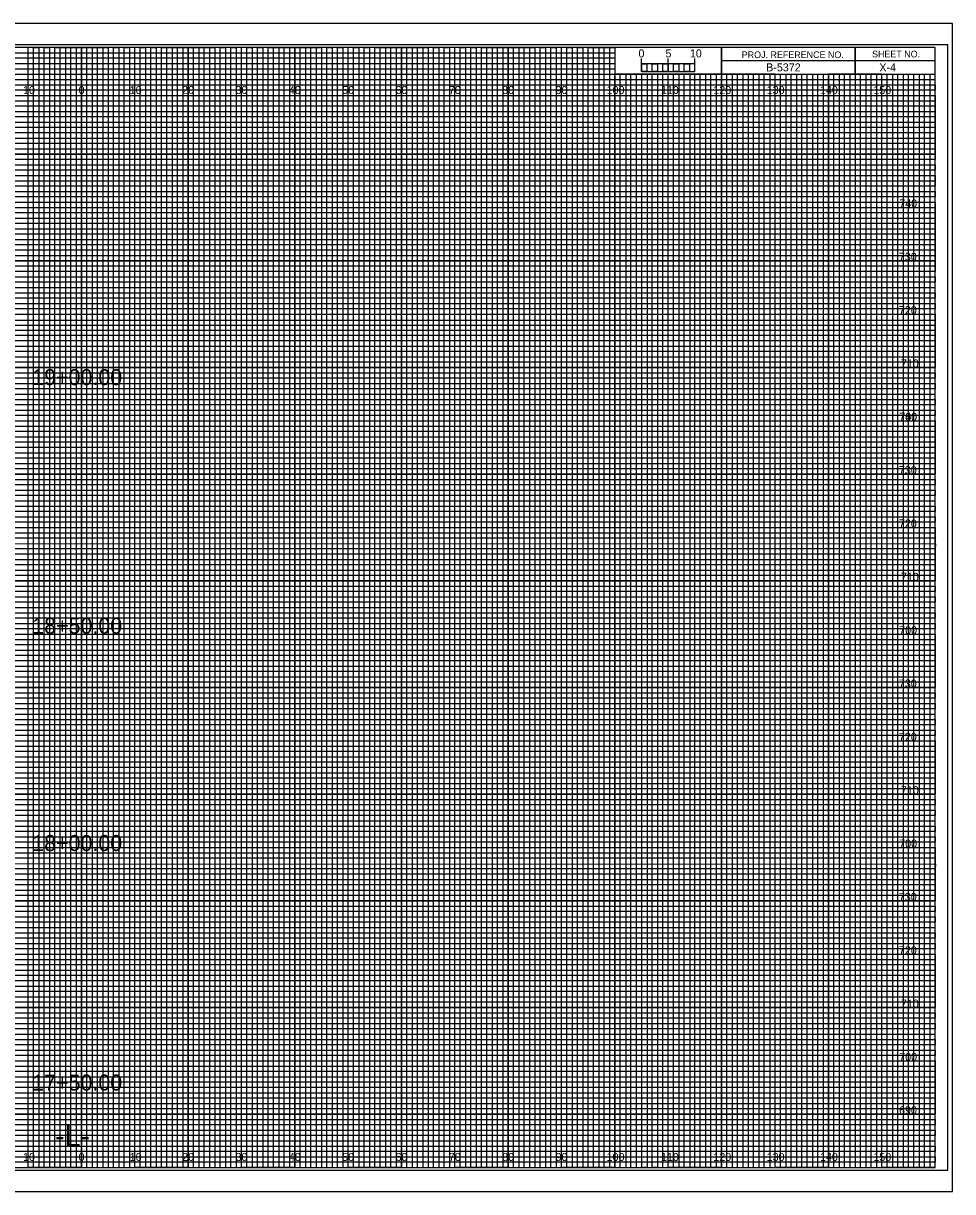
# Model space of a CAD drawing. Extents: x -98 to 717, y -10 to 1974.
# Drawn here: x 149.1 to 323.3, y 655.5 to 874.5 of the extents above; entities that cross this region are included whole.
import ezdxf

# ---------------------------------------------------------------- set-up
doc = ezdxf.new("R2010")
doc.units = 0
for name, color, linetype in [('Default', 7, 'Continuous'), ('Exist XS Center Line Elevation Label', 7, 'Continuous'), ('Prop CMT Conc Surface', 7, 'Continuous'), ('Prop CMT Concrete Structures', 7, 'Continuous'), ('Prop CMT Pvmt Course 1', 7, 'Continuous'), ('Prop CMT Pvmt Course 1 CG', 7, 'Continuous'), ('Prop CMT Pvmt Course 2', 7, 'Continuous'), ('Prop CMT Pvmt Course 3', 7, 'Continuous'), ('Prop CMT Pvmt Surface', 7, 'Continuous'), ('Prop CMT Pvmt Surface Shoulder', 7, 'Continuous'), ('Prop CMT Shld Paved Course 1', 7, 'Continuous'), ('Prop CMT Shld Paved Course 2', 7, 'Continuous'), ('Prop CMT Shld Paved Course 3', 7, 'Continuous'), ('Prop CMT Slope Grass', 7, 'Continuous'), ('Prop CMT Subgrade Earthwork', 7, 'Continuous'), ('Prop XS Earthwork Shape', 7, 'Continuous'), ('Prop XS Elevation Labels', 7, 'Continuous'), ('Typical Curb CELL', 7, 'Continuous')]:
    doc.layers.add(name, color=color, linetype=linetype)

msp = doc.modelspace()

# ---------------------------------------------------------------- linework, layer by layer
at = {"layer": 'Default'}
msp.add_lwpolyline([(-13.4, 655.5), (323.3, 655.5), (323.3, 874.5), (-13.4, 874.5)], close=True, dxfattribs=at)
at = {"layer": 'Exist XS Center Line Elevation Label'}
for p, q in [((0, 869), (260, 869)), ((260, 867.98), (0, 867.98)), ((260, 869), (260, 867.98)), ((0, 867), (260, 867)), ((260, 865.89), (0, 865.89)), ((260, 867), (260, 865.89)), ((0, 864), (320, 864))]:
    msp.add_line(p, q, dxfattribs=at)
for points in [[(0, 863), (270, 863), (320, 863), (320, 862), (0, 862)], [(0, 861), (320, 861), (320, 859), (0, 859)], [(0, 858), (320, 858), (320, 857), (0, 856.98)], [(0, 856), (320, 856), (320, 854), (0, 854)], [(0, 853), (320, 853), (320, 852), (0, 852)], [(0, 851), (320, 851), (320, 849), (0, 849)], [(0, 848), (320, 848), (320, 847), (0, 847)], [(0, 846), (320, 846), (320, 844), (0, 844)], [(0, 843), (320, 843), (320, 842), (0, 842)], [(0, 841), (320, 841), (320, 839), (0, 839)], [(0, 838), (320, 838), (320, 837), (0, 837)], [(0, 836), (320, 836), (320, 833.95), (320, 833), (320, 832), (0, 832)], [(0, 834), (320, 834), (320, 833), (0, 833)], [(0, 831), (320, 831), (320, 829), (0, 829.03)], [(0, 829.03), (320, 829), (320, 828), (0, 828)], [(0, 827), (320, 827), (320, 826), (0, 826)], [(0, 824), (320, 824), (320, 823), (0, 823)], [(0, 822), (320, 822), (320, 821), (0, 821)], [(-0.07, 818.89), (320, 818.89), (320, 817.88), (-0.07, 817.88)], [(0, 817), (320, 817), (320, 816), (0, 816)], [(0, 814), (320, 814), (320, 813), (0, 813)], [(0, 812), (320, 812), (320, 811), (0, 811)], [(0, 809), (320, 809), (320, 808), (0, 808)], [(0, 807), (320, 807), (320, 806), (0, 806)], [(0, 804), (320, 804), (320, 803), (0, 803)], [(0, 802), (320, 802), (320, 801), (0, 801)], [(0, 799), (320, 799), (319.99, 797.98), (0, 798)], [(0, 797), (320, 797), (320, 796), (0, 796)], [(0, 794), (320, 794), (320, 793), (0, 793)], [(0, 792), (320, 792), (320, 791), (0, 791)], [(0, 789), (320, 789), (320, 788), (0, 788)], [(0, 787), (320, 787), (320, 786), (0, 786)], [(0, 784), (320, 784), (320, 783), (0, 783)], [(0, 782), (320, 782), (320, 781), (0, 781)], [(0, 779), (320, 779), (320, 778), (0, 778)], [(0, 776.99), (320.07, 776.91), (320, 776), (0, 776)], [(0, 774), (320, 774), (320, 773), (0, 773)], [(0, 772), (320, 772), (320, 771), (0, 771)], [(0, 769), (320, 769), (320, 768), (0, 768)], [(0, 767), (320, 767), (320, 766), (0, 766)], [(0, 764), (320, 764), (320, 763), (0, 763)], [(0, 762), (320, 762), (320, 761), (0, 761)], [(0, 759), (320, 759), (320, 758), (0, 758)], [(0, 757), (320, 757), (320, 756), (0, 756)], [(0, 754), (320, 754), (320, 753), (0, 753)], [(0, 752), (320, 752), (320, 751), (0, 751)], [(0, 749), (320, 749), (320, 748), (0, 748)], [(0, 747), (320, 747), (320, 746), (0, 746)], [(0, 744), (320, 744), (320, 743), (0, 743)], [(0, 742), (320, 742), (320, 741), (0, 741)], [(0, 739), (320, 739), (319.99, 737.98), (0, 738)], [(0, 737), (320, 737), (320, 736), (0, 736)], [(0, 734), (320, 734), (320, 733), (0, 733)], [(0, 732), (320, 732), (320, 731), (0, 731)], [(0, 729), (320, 729), (320, 728), (0, 728)], [(0, 727), (320, 727), (320, 726), (0, 726)], [(0, 724), (320, 724), (320, 723), (0, 723)], [(0, 722), (320, 722), (320, 721), (0, 721)], [(0, 719), (320, 719), (320, 718), (0, 718)], [(0, 716.99), (320.07, 716.91), (320, 716), (0, 716)], [(0, 714), (320, 714), (320, 713), (0, 713)], [(0, 712), (320, 712), (320, 711), (0, 711)], [(0, 709), (320, 709), (320, 708), (0, 708)], [(0, 707), (320, 707), (320, 706), (0, 706)], [(0, 704), (320, 704), (320, 703), (0, 703)], [(0, 702), (320, 702), (320, 701), (0, 701)], [(0, 699), (320, 699), (320, 698), (0, 698)], [(0, 697), (320, 697), (320, 696), (0, 696)], [(0, 694), (320, 694), (320, 693), (0, 693)], [(0, 692), (320, 692), (320, 691), (0, 691)], [(0, 689), (320, 689), (320, 688), (0, 688)], [(0, 687), (320, 687), (320, 686), (0, 686)], [(0, 684), (320, 684), (320, 683), (0, 683)], [(0, 682), (320, 682), (320, 681), (0, 681)], [(0, 679), (320, 679), (320, 678), (0, 678)], [(0, 677), (320, 677), (320, 676), (0, 676)], [(0, 674), (320, 674), (320, 673), (0, 673)], [(0, 672), (320, 672), (320, 671), (0, 671)], [(0, 669), (320, 669), (320, 668), (0, 668)], [(0, 667), (320, 667), (320, 666), (0, 666)], [(0, 664), (320, 664), (320, 663), (0, 663)], [(0, 662), (320, 662), (320, 661), (0, 661)]]:
    msp.add_lwpolyline(points, dxfattribs=at)
at = {"layer": 'Prop CMT Conc Surface'}
for p, q in [((305, 870), (305, 865)), ((305, 865), (305, 870)), ((280, 867.5), (280, 865)), ((320, 867.49), (280, 867.49)), ((280, 865), (320, 865))]:
    msp.add_line(p, q, dxfattribs=at)
for points in [[(320, 870), (0, 870), (0, 660), (320, 660)], [(280, 870), (260, 870), (260, 865.03), (280, 865.03)], [(320, 870), (280, 870), (280, 865), (320, 865)]]:
    msp.add_lwpolyline(points, close=True, dxfattribs=at)
at = {"layer": 'Prop CMT Concrete Structures'}
for p, q in [((150, 660), (150, 870)), ((160, 660), (160, 870)), ((170, 660), (170, 870)), ((180, 660), (180, 870)), ((190, 660), (190, 870)), ((200, 660), (200, 870)), ((210, 660), (210, 870)), ((220, 660), (220, 870)), ((230, 660), (230, 870)), ((240, 660), (240, 870)), ((250, 660), (250, 870)), ((260, 660), (260, 864.69)), ((270, 660), (270, 864.69)), ((280, 660), (280, 864.69)), ((290, 660), (290, 864.69)), ((300, 660), (300, 864.69)), ((310, 660), (310, 864.69)), ((0, 860), (320, 860)), ((0, 850), (320, 850)), ((0, 840), (320, 840)), ((0, 830), (320, 830)), ((0, 820), (320, 820)), ((0, 810), (320, 810)), ((0, 800), (320, 800)), ((0, 790), (320, 790)), ((0, 780), (320, 780)), ((0, 770), (320, 770)), ((0, 760), (320, 760)), ((0, 750), (320, 750)), ((0, 740), (320, 740)), ((0, 730), (320, 730)), ((0, 720), (320, 720)), ((0, 710), (320, 710)), ((0, 700), (320, 700)), ((0, 690), (320, 690)), ((0, 680), (320, 680)), ((0, 670), (320, 670))]:
    msp.add_line(p, q, dxfattribs=at)
at = {"layer": 'Prop CMT Pvmt Course 2'}
msp.add_lwpolyline([(-13.4, 655.5), (323.3, 655.5), (323.3, 874.5), (-13.4, 874.5)], close=True, dxfattribs=at)
at = {"layer": 'Prop CMT Pvmt Course 3'}
msp.add_lwpolyline([(-10.8, 659.5), (322.4, 659.5), (322.4, 870.5), (-10.8, 870.5)], close=True, dxfattribs=at)
at = {"layer": 'Prop CMT Pvmt Surface'}
for p, q in [((323.3, 874.5), (-13.4, 874.5)), ((-13.4, 655.5), (323.3, 655.5))]:
    msp.add_line(p, q, dxfattribs=at)
at = {"layer": 'Prop CMT Slope Grass'}
for p, q in [((265, 865.49), (265, 867.9)), ((265, 866.9), (265, 867.9)), ((270, 865.49), (270, 867.9)), ((275, 865.49), (275, 867.9)), ((275, 866.9), (275, 867.9))]:
    msp.add_line(p, q, dxfattribs=at)
for points in [[(275, 866.9), (265, 866.9), (265, 865.49), (275, 865.49)], [(265, 866.9), (266, 866.9), (266, 865.49), (265, 865.49)], [(267, 866.9), (268, 866.9), (268, 865.49), (267, 865.49)], [(269, 866.9), (270, 866.9), (270, 865.49), (269, 865.49)], [(271, 866.9), (272, 866.9), (272, 865.49), (271, 865.49)], [(273, 866.9), (274, 866.9), (274, 865.49), (273, 865.49)]]:
    msp.add_lwpolyline(points, close=True, dxfattribs=at)
at = {"layer": 'Prop CMT Subgrade Earthwork'}
for p, q in [((267, 865), (266.01, 865)), ((266.01, 865), (266.01, 660)), ((267, 660), (267, 865)), ((269, 865), (268, 865)), ((268, 865), (268, 660)), ((269, 660), (269, 865)), ((266.01, 660), (265, 660)), ((268, 660), (267, 660))]:
    msp.add_line(p, q, dxfattribs=at)
for points in [[(150, 660), (151, 660), (151, 870), (152, 870), (152, 660)], [(152, 660), (153, 660), (153, 870), (154, 870), (154, 660)], [(155, 660), (156, 660), (156, 870), (157, 870), (157, 660)], [(157, 660), (158, 660), (158, 870), (159, 870), (159, 660)], [(160, 660), (161, 660), (161, 870), (162, 870), (162, 660)], [(162, 660), (163, 660), (163, 870), (164, 870), (164, 660)], [(165, 660), (166, 660), (166, 870), (167, 870), (167, 660)], [(167, 660), (168, 660), (168, 870), (169, 870), (169, 660)], [(170, 660), (171, 660), (171, 870), (172, 870), (172, 660)], [(172, 660), (173, 660), (173, 870), (174, 870), (174, 660)], [(175, 660), (176, 660), (176, 870), (177, 870), (177, 660)], [(177, 660), (178, 660), (178, 870), (179, 870), (179, 660)], [(180, 660), (181, 660), (181, 870), (182, 870), (182, 660)], [(182, 660), (183, 660), (183, 870), (184, 870), (184, 660)], [(185, 660), (186, 660), (186, 870), (187, 870), (187, 660)], [(187, 660), (188, 660), (188, 870), (189, 870), (189, 660)], [(190, 660), (191, 660), (191, 870), (192, 870), (192, 660)], [(192, 660), (193, 660), (193, 870), (194, 870), (194, 660)], [(195, 660), (196, 660), (196, 870), (197, 870), (197, 660)], [(197, 660), (198, 660), (198, 870), (199, 870), (199, 660)], [(200, 660), (201, 660), (201, 870), (202, 870), (202, 660)], [(202, 660), (203, 660), (203, 870), (204, 870), (204, 660)], [(205, 660), (206, 660), (206, 870), (207, 870), (207, 660)], [(207, 660), (208, 660), (208, 870), (209, 870), (209, 660)], [(210, 660), (211, 660), (211, 870), (212, 870), (212, 660)], [(212, 660), (213, 660), (213, 870), (214, 870), (214, 660)], [(215, 660), (216, 660), (216, 870), (217, 870), (217, 660)], [(217, 660), (218, 660), (218, 870), (219, 870), (219, 660)], [(220, 660), (221, 660), (221, 870), (222, 870), (222, 660)], [(222, 660), (223, 660), (223, 870), (224, 870), (224, 660)], [(225, 660), (226, 660), (226, 870), (227, 870), (227, 660)], [(227, 660), (228, 660), (228, 870), (229, 870), (229, 660)], [(230, 660), (231, 660), (231, 870), (232, 870), (232, 660)], [(232, 660), (233, 660), (233, 870), (234, 870), (234, 660)], [(235, 660), (236, 660), (236, 870), (237, 870), (237, 660)], [(237, 660), (238, 660), (238, 870), (239, 870), (239, 660)], [(240, 660), (241, 660), (241, 870), (242, 870), (242, 660)], [(242, 660), (243, 660), (243, 870), (244, 870), (244, 660)], [(245, 660), (246, 660), (246, 870), (247, 870), (247, 660)], [(247, 660), (248, 660), (248, 870), (249, 870), (249, 660)], [(250, 660), (251, 660), (251, 870), (252, 870), (252, 660)], [(252, 660), (253, 660), (253, 870), (254, 870), (254, 660)], [(255, 660), (256, 660), (256, 870), (257, 870), (257, 660)], [(257, 660), (258, 660), (258, 870), (259, 870), (259, 660)], [(260, 660), (261, 660), (261, 865), (262.02, 865), (262.02, 660)], [(262, 660), (263, 660), (263, 865), (263.99, 865), (263.99, 660)], [(270, 660), (270.98, 660), (270.98, 865), (272, 865), (272, 660)], [(272, 660), (273, 660), (273, 865), (274.05, 865), (274.05, 660)], [(275, 660), (276, 660), (276, 865), (277, 865), (277, 660)], [(277, 660), (278, 660), (278, 865), (279, 865), (279, 660)], [(280, 660), (281, 660), (281, 865), (282, 865), (282, 660)], [(282, 660), (283, 660), (283, 865), (284, 865), (284, 660)], [(285, 660), (286, 660), (286, 865), (287, 865), (287, 660)], [(287, 660), (288, 660), (288, 865), (289, 865), (289, 660)], [(290, 660), (291, 660), (291, 865), (292, 865), (292, 660)], [(292, 660), (293, 660), (293, 865), (294, 865), (294, 660)], [(295, 660), (296, 660), (296, 865), (297, 865), (297, 660)], [(297, 660), (298, 660), (298, 865), (299, 865), (299, 660)], [(300, 660), (301, 660), (301, 865), (302, 865), (302, 660)], [(302, 660), (303, 660), (303, 865), (304, 865), (304, 660)], [(305, 660), (306, 660), (306, 865), (307, 865), (307, 660)], [(307, 660), (308, 660), (308, 865), (309, 865), (309, 660)], [(310, 660), (311, 660), (311, 865), (312, 865), (312, 660)], [(312, 660), (313, 660), (313, 865), (314, 865), (314, 660)], [(315, 660), (316, 660), (316, 865), (317, 865), (317, 660)], [(317, 660), (318, 660), (318, 865), (319, 865), (319, 660)]]:
    msp.add_lwpolyline(points, dxfattribs=at)
at = {"layer": 'Prop XS Elevation Labels'}
for p, q in [((150, 870), (140, 870)), ((150, 660), (150, 870)), ((170, 870), (160, 870)), ((160, 870), (160, 660)), ((170, 660), (170, 870)), ((190, 870), (180, 870)), ((180, 870), (180, 660)), ((190, 660), (190, 870)), ((210, 870), (200, 870)), ((200, 870), (200, 660)), ((210, 660), (210, 870)), ((230, 870), (220, 870)), ((220, 870), (220, 660)), ((230, 660), (230, 870)), ((250, 870), (240, 870)), ((240, 870), (240, 660)), ((250, 660), (250, 870)), ((260, 870), (260, 660)), ((270, 660), (270, 865)), ((290, 865), (280, 865)), ((280, 865), (280, 660)), ((290, 660), (290, 865)), ((310, 865), (300, 865)), ((300, 865), (300, 660)), ((310, 660), (310, 865)), ((160, 660), (150, 660)), ((180, 660), (170, 660)), ((200, 660), (190, 660)), ((220, 660), (210, 660)), ((240, 660), (230, 660)), ((260, 660), (250, 660)), ((280, 660), (270, 660)), ((300, 660), (290, 660)), ((320, 660), (310, 660)), ((320, 660), (320, 660))]:
    msp.add_line(p, q, dxfattribs=at)
for points in [[(0, 860), (320, 860), (320, 850), (0, 850)], [(0, 840), (320, 840), (320, 830), (0, 830)], [(0, 820), (320, 820), (320, 810), (0, 810)], [(0, 800), (320, 800), (320, 790), (0, 790)], [(0, 780), (320, 780), (320, 770), (0, 770)], [(0, 760), (320, 760), (320, 750), (0, 750)], [(0, 740), (320, 740), (320, 730), (0, 730)], [(0, 720), (320, 720), (320, 710), (0, 710)], [(0, 700), (320, 700), (320, 690), (0, 690)], [(0, 680), (320, 680), (320, 670), (0, 670)]]:
    msp.add_lwpolyline(points, dxfattribs=at)
at = {"layer": 'Typical Curb CELL'}
for points in [[(145, 660), (155, 660), (155, 870), (165, 870), (165, 660), (175, 660), (175, 870), (185, 870), (185, 660), (195, 660), (195, 870), (205, 870), (205, 660), (215, 660), (215, 870), (225, 870), (225, 660), (235, 660), (235, 870), (245, 870), (245, 660), (255, 660), (255, 870), (259.93, 870), (260, 870), (260, 865), (264.99, 865), (264.99, 660), (275, 660), (275, 865), (285, 865), (285, 660), (295, 660), (295, 865), (305, 865), (305, 660), (315, 660), (315, 865)], [(0, 865), (275, 865)], [(0, 845), (320, 845), (320, 855), (0, 855)], [(0, 825), (320, 825), (320, 835), (0, 835)], [(0, 805), (320, 805), (320, 815), (0, 815)], [(0, 785), (320, 785), (320, 795), (0, 795)], [(0, 765), (320, 765), (320, 775), (0, 775)], [(0, 745), (320, 745), (320, 755), (0, 755)], [(0, 725), (320, 725), (320, 735), (0, 735)], [(0, 705), (320, 705), (320, 715), (0, 715)], [(0, 685), (320, 685), (320, 695), (0, 695)], [(0, 665), (320, 665), (320, 675), (0, 675)]]:
    msp.add_lwpolyline(points, dxfattribs=at)

# ---------------------------------------------------------------- texts
at = {"layer": 'Prop CMT Conc Surface'}
for s, p in [('PROJ. REFERENCE NO.', (283.77, 867.99)), ('SHEET NO.', (308.19, 868.12))]:
    msp.add_text(s, height=1.25, dxfattribs=at).set_placement(p)
at = {"layer": 'Prop CMT Pvmt Course 1'}
for s, p in [('19+00.00', (150.77, 806.68)), ('18+50.00', (150.77, 760.09)), ('18+00.00', (150.77, 719.35)), ('17+50.00', (150.77, 674.45))]:
    msp.add_text(s, height=3, dxfattribs=at).set_placement(p)
at = {"layer": 'Prop CMT Pvmt Course 1 CG'}
for s, p in [('740', (313.3, 840)), ('730', (313.22, 830)), ('720', (313.23, 820)), ('710', (313.61, 810)), ('700', (313.28, 800)), ('740', (313.3, 800)), ('730', (313.22, 790)), ('720', (313.23, 780)), ('710', (313.61, 770)), ('700', (313.28, 760)), ('730', (313.22, 750)), ('720', (313.23, 740)), ('710', (313.61, 730)), ('700', (313.28, 720)), ('730', (313.22, 710)), ('720', (313.23, 700)), ('710', (313.61, 690)), ('700', (313.28, 680)), ('690', (313.26, 670))]:
    msp.add_text(s, height=1.5, dxfattribs=at).set_placement(p)
at = {"layer": 'Prop CMT Pvmt Surface Shoulder'}
for s, p in [('5', (269.47, 868.12)), ('10', (274.04, 868.12))]:
    msp.add_text(s, height=1.5, dxfattribs=at).set_placement(p)
at = {"layer": 'Prop CMT Shld Paved Course 1'}
msp.add_text('X-4', height=1.5, dxfattribs=at).set_placement((309.57, 865.5))
at = {"layer": 'Prop CMT Shld Paved Course 2'}
msp.add_text('B-5372', height=1.5, dxfattribs=at).set_placement((288.34, 865.5))
at = {"layer": 'Prop CMT Shld Paved Course 3'}
msp.add_text('-L-', height=4, dxfattribs=at).set_placement((155.06, 664))
at = {"layer": 'Prop CMT Slope Grass'}
msp.add_text('0', height=1.5, dxfattribs=at).set_placement((264.41, 868.12))
at = {"layer": 'Prop XS Earthwork Shape'}
for s, p in [('10', (149.04, 861.25)), ('0', (159.45, 861.25)), ('0', (159.45, 861.25)), ('10', (169.04, 861.25)), ('20', (178.86, 861.25)), ('30', (188.86, 861.25)), ('40', (198.86, 861.25)), ('50', (208.86, 861.25)), ('60', (218.86, 861.25)), ('70', (228.86, 861.25)), ('80', (238.86, 861.25)), ('90', (248.86, 861.25)), ('100', (258.44, 861.25)), ('110', (268.62, 861.25)), ('120', (278.44, 861.25)), ('130', (288.44, 861.25)), ('140', (298.44, 861.25)), ('150', (308.44, 861.25)), ('10', (149.04, 661.25)), ('0', (159.45, 661.25)), ('0', (159.45, 661.25)), ('10', (169.04, 661.25)), ('20', (178.86, 661.25)), ('30', (188.86, 661.25)), ('40', (198.86, 661.25)), ('50', (208.86, 661.25)), ('60', (218.86, 661.25)), ('70', (228.86, 661.25)), ('80', (238.86, 661.25)), ('90', (248.86, 661.25)), ('100', (258.44, 661.25)), ('110', (268.62, 661.25)), ('120', (278.44, 661.25)), ('130', (288.44, 661.25)), ('140', (298.44, 661.25)), ('150', (308.44, 661.25))]:
    msp.add_text(s, height=1.5, dxfattribs=at).set_placement(p)

doc.saveas('drawing.dxf')
